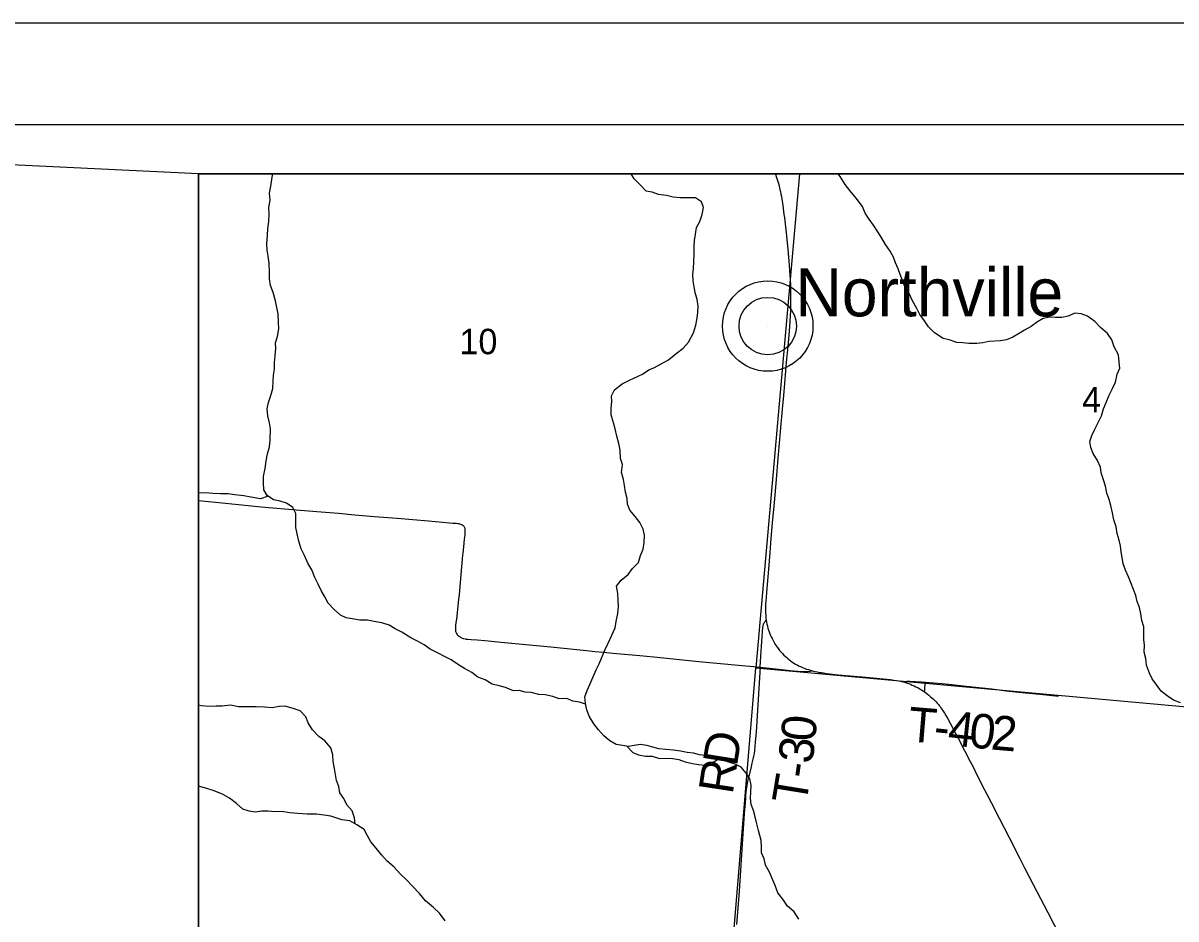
# Model space of a CAD drawing. Extents: x 0 to 1067, y 0 to 440.
# Drawn here: x 113.7 to 227.4, y 351.6 to 440 of the extents above; entities that cross this region are included whole.
import ezdxf

# ---------------------------------------------------------------- set-up
doc = ezdxf.new("R2010")
doc.units = 0
for name, color, linetype in [('GM_X_Minor_River', 7, 'Continuous'), ('GM_X_Section', 7, 'Continuous'), ('GM_X_Section_Text', 7, 'Continuous'), ('GM_X_State_Route', 7, 'Continuous'), ('GM_X_Township_Road', 7, 'Continuous'), ('GM_X_Township_Road_Text', 7, 'Continuous'), ('GM_X_Unincorporated', 7, 'Continuous'), ('GM_X_Unincorporated_Location', 7, 'Continuous'), ('GM_X_Unincorporated_Text', 7, 'Continuous'), ('GM_X_US_Shield', 7, 'Continuous'), ('SC_Scratch1', 7, 'Continuous'), ('SH_Border', 7, 'Continuous'), ('SH_Cut_Line', 7, 'Continuous'), ('SH_Text', 7, 'Continuous')]:
    doc.layers.add(name, color=color, linetype=linetype)

msp = doc.modelspace()

# ---------------------------------------------------------------- linework, layer by layer
at = {"layer": 'GM_X_Minor_River'}
for points in [[(138.15, 423.91), (138.27, 424.79), (138.34, 425.11)], [(173.11, 393.74), (173.02, 394.38), (172.92, 394.98), (172.72, 395.67), (172.83, 396.46), (172.62, 397.06), (172.6, 397.88), (172.46, 398.54), (172.28, 399.25), (172.09, 399.98), (171.93, 400.56), (171.7, 401.34), (171.7, 402.02), (171.76, 402.65), (171.73, 403.22), (172.05, 403.81), (172.79, 404.42), (173.51, 404.78), (174.8, 405.38), (175.41, 405.8), (175.98, 406.03), (176.63, 406.4), (177.35, 406.78), (178.12, 407.4), (178.82, 407.94), (179.34, 408.52), (179.84, 409.44), (180.05, 410.2), (180.2, 410.88), (180.24, 411.45), (180.28, 412.08), (180.19, 412.72), (180, 413.41), (179.88, 413.98), (179.79, 414.58), (179.76, 415.21), (179.82, 415.8), (179.87, 416.46), (179.89, 417.23), (179.89, 417.98), (179.93, 418.55), (180.04, 419.16), (180.13, 419.82), (180.46, 420.44), (180.69, 421.12), (180.82, 421.8), (180.63, 422.37), (180.01, 422.77), (179.39, 422.77), (178.51, 422.77), (177.82, 422.84), (177.15, 423), (176.37, 423.09), (175.74, 423.31), (175.16, 423.42), (174.58, 424.03), (173.96, 424.64), (173.68, 425.11)], [(203.61, 409.43), (203.01, 410.04), (202.6, 410.62), (202.16, 411.25), (201.84, 411.85), (201.43, 412.59), (201.11, 413.31), (200.72, 413.93), (200.48, 414.53), (200.21, 415.2), (200.02, 415.77), (199.76, 416.35), (199.55, 416.92), (199.23, 417.5), (198.75, 418.15), (198.4, 418.77), (198.01, 419.4), (197.57, 420.05), (197.14, 420.67), (196.77, 421.25), (196.49, 421.9), (195.88, 422.71), (195.26, 423.48), (194.78, 424.09), (194.28, 424.87), (194.11, 425.11)], [(169.19, 372.8), (168.59, 373.01), (167.93, 373.1), (167.32, 373.37), (166.59, 373.34), (165.96, 373.57), (165.21, 373.73), (164.58, 373.77), (163.81, 373.95), (163.22, 373.99), (162.63, 374.17), (162.06, 374.14), (161.3, 374.44), (160.66, 374.62), (159.98, 374.77), (159.27, 375.21), (158.57, 375.46), (157.97, 375.95), (157.25, 376.34), (156.56, 376.77), (155.93, 377.17), (155.35, 377.47), (154.57, 377.88), (153.87, 378.24), (153.25, 378.67), (152.53, 379.05), (151.95, 379.35), (151.05, 379.9), (150.4, 380.23), (149.82, 380.59), (149.1, 380.82), (148.51, 380.95), (147.69, 381.09), (146.92, 381.11), (146.17, 381.23), (145.58, 381.34), (145, 381.58), (144.4, 382.15), (143.8, 382.76), (143.46, 383.41), (143.09, 384.03), (142.81, 384.65), (142.47, 385.32), (142.17, 386.06), (141.78, 386.73), (141.46, 387.47), (141.14, 388.14), (140.89, 388.9), (140.75, 389.63), (140.61, 390.23), (140.61, 390.91), (140.6, 391.61), (140.3, 392.21), (139.68, 392.64), (139.07, 392.84), (138.41, 392.98), (137.79, 393.38), (137.46, 393.96), (137.42, 394.64), (137.43, 395.28), (137.59, 396.07), (137.68, 396.8), (137.82, 397.52), (138, 398.2), (138.09, 398.88), (138.1, 399.97), (138.02, 400.58), (137.86, 401.25), (137.79, 401.95), (137.92, 402.56), (138.15, 403.26), (138.33, 403.96), (138.37, 404.66), (138.39, 405.28), (138.5, 405.86), (138.52, 406.5), (138.58, 407.18), (138.65, 407.9), (138.6, 408.47), (138.8, 409.08), (138.94, 409.83), (138.89, 410.49), (138.87, 411.31), (138.75, 411.95), (138.59, 412.61), (138.36, 413.41), (138.11, 414.12), (138.01, 414.78), (138.01, 415.4), (137.97, 416.31), (137.87, 416.99), (137.78, 417.59), (137.75, 418.22), (137.82, 419.06), (137.84, 419.7), (137.95, 420.44), (137.97, 421.15), (137.95, 421.8), (138.08, 422.53), (138.01, 423.23), (138.15, 423.91)], [(227.85, 372.93), (227.17, 373.2), (226.53, 373.65), (225.95, 374.1), (225.51, 374.68), (225.05, 375.31), (224.79, 375.88), (224.52, 376.67), (224.45, 377.31), (224.29, 377.95), (224.31, 378.63), (224.23, 379.2), (224.23, 379.86), (224.25, 380.45), (224.04, 381.05), (223.94, 381.72), (223.8, 382.36), (223.57, 382.93), (223.45, 383.53), (223.22, 384.13), (223.01, 384.73), (222.73, 385.37), (222.43, 386.02), (222.22, 386.64), (222.1, 387.28), (222.01, 387.85), (221.93, 388.42), (221.81, 388.99), (221.6, 389.66), (221.51, 390.3), (221.28, 391.01), (221.14, 391.7), (220.98, 392.41), (220.81, 393), (220.58, 393.63), (220.47, 394.31), (220.26, 394.95), (220.05, 395.62), (219.98, 396.19), (219.68, 396.84), (219.26, 397.55), (219.03, 398.13), (218.93, 398.72), (219.11, 399.33), (219.4, 399.94), (219.72, 400.54), (220.06, 401.26), (220.26, 401.96), (220.53, 402.57), (220.82, 403.29), (221.16, 403.94), (221.45, 404.56), (221.61, 405.38), (221.86, 405.96), (221.81, 406.55), (221.74, 407.28), (221.33, 408.07), (221.08, 408.74), (220.66, 409.38), (219.97, 409.97), (219.4, 410.56), (218.69, 411.1), (218.06, 411.33), (217.44, 411.37), (216.77, 411.09), (216.16, 410.97), (215.52, 410.97), (214.95, 410.99), (214.33, 410.87), (213.75, 410.52), (213.12, 410.08), (212.48, 409.72), (211.89, 409.33), (211.32, 409.02), (210.69, 408.75), (210.12, 408.65), (208.96, 408.59), (208.36, 408.45), (207.77, 408.38), (206.99, 408.38), (206.38, 408.44), (205.79, 408.48), (205.05, 408.75), (204.46, 408.89), (203.61, 409.43)], [(137.88, 393.32), (137.12, 393.08), (136.17, 393.23), (135.49, 393.36), (134.6, 393.46), (133.95, 393.57), (133.17, 393.55), (132.42, 393.59), (131.69, 393.66), (131.01, 393.61), (131, 393.61)], [(190.22, 351.6), (189.77, 352.32), (189.1, 352.89), (188.64, 353.56), (188.16, 354.19), (187.88, 354.91), (187.59, 355.62), (187.33, 356.25), (186.94, 356.94), (186.8, 357.54), (186.54, 358.16), (186.54, 358.73), (186.49, 359.37), (186.25, 360.36), (186.06, 361), (185.92, 361.69), (185.73, 362.31), (185.52, 362.91), (185.45, 363.53), (185.47, 364.14), (185.53, 364.82), (185.37, 365.44), (185.02, 366.02), (184.54, 366.61), (183.93, 366.9), (183.32, 367.08), (182.47, 367.35), (181.83, 367.42), (181.18, 367.71), (180.41, 367.82), (179.82, 367.98), (179.19, 368.04), (178.55, 368.18), (177.87, 368.29), (177.1, 368.33), (176.42, 368.4), (175.83, 368.58), (175.22, 368.73), (174.59, 368.82), (173.99, 368.75), (173.42, 368.65), (172.83, 368.74), (172.2, 368.82), (171.57, 369.18), (170.99, 369.7), (170.46, 370.29), (170, 370.87), (169.55, 371.64), (169.31, 372.24), (169.17, 372.88), (169.1, 373.52), (169.35, 374.17), (169.59, 374.76), (169.91, 375.45), (170.23, 376.19), (170.52, 376.78), (170.74, 377.36), (171.08, 378.15), (171.4, 378.82), (171.76, 379.63), (172.1, 380.33), (172.19, 380.98), (172.37, 381.75), (172.42, 382.46), (172.41, 383.07), (172.36, 383.73), (172.25, 384.44), (172.7, 385.06), (173.37, 385.59), (173.8, 386.19), (174.39, 386.79), (174.61, 387.49), (174.88, 388.09), (174.95, 388.77), (174.99, 389.48), (174.87, 390.07), (174.53, 390.72), (174.09, 391.33), (173.56, 391.96), (173.31, 392.53), (173.28, 393.1), (173.11, 393.74)], [(146.47, 361), (146.41, 361.59), (146.16, 362.28), (145.65, 362.89), (145.35, 363.49), (144.96, 364.08), (144.86, 364.69), (144.63, 365.29), (144.53, 365.87), (144.42, 366.48), (144.3, 367.17), (144.25, 367.81), (144.07, 368.5), (143.47, 369.2), (142.89, 369.63), (142.25, 370.29), (141.84, 370.98), (141.58, 371.56), (141.05, 372.17), (140.33, 372.39), (139.56, 372.62), (138.95, 372.57), (138.28, 372.46), (137.51, 372.5), (136.69, 372.55), (135.85, 372.55), (134.94, 372.54), (134.15, 372.7), (133.35, 372.63), (132.76, 372.63), (132.07, 372.58), (131.32, 372.65), (131, 372.71)], [(173.24, 368.69), (173.26, 368.66), (173.83, 368.05), (174.42, 367.82), (175.08, 367.69), (175.74, 367.67), (176.46, 367.46), (177.17, 367.49), (177.8, 367.45), (178.39, 367.36), (179, 367.11), (179.72, 366.96), (180.34, 366.87), (180.92, 366.78), (181.5, 366.93), (182.19, 367.36), (182.21, 367.38)], [(155.34, 351.45), (154.77, 352.2), (154.19, 352.76), (153.41, 353.4), (152.82, 354.13), (152.09, 354.88), (151.52, 355.47), (150.92, 356.03), (150.26, 356.78), (149.63, 357.32), (149.06, 357.96), (148.53, 358.61), (148.01, 359.22), (147.66, 359.82), (147.34, 360.45), (146.64, 360.9), (145.93, 361.31), (145.15, 361.4), (144.05, 361.76), (143.39, 361.87), (142.64, 361.96), (141.73, 361.96), (140.8, 362.02), (140.03, 362.09), (139.21, 362.22), (138.55, 362.18), (137.87, 362.27), (137.21, 362.26), (136.59, 362.17), (136, 362.25), (135.37, 362.46), (134.77, 363.02), (134.06, 363.54), (133.39, 363.93), (132.44, 364.28), (131.83, 364.48), (131, 364.72)]]:
    msp.add_lwpolyline(points, dxfattribs=at)
at = {"layer": 'GM_X_Section'}
msp.add_lwpolyline([(185.99, 376.41), (246.65, 370.91), (240.78, 310.99), (180.98, 316.33)], close=True, dxfattribs=at)
at = {"layer": 'GM_X_State_Route'}
for points in [[(187.91, 425.11), (187.92, 425.08), (187.99, 424.87), (188.06, 424.67), (188.12, 424.48), (188.17, 424.26), (188.23, 424.07), (188.27, 423.9), (188.31, 423.74), (188.35, 423.56), (188.4, 423.39), (188.45, 423.13), (188.5, 422.89), (188.55, 422.62), (188.61, 422.23), (188.64, 422), (188.75, 421.13), (188.8, 420.82), (188.88, 420.18), (188.96, 419.29), (189.09, 418.03), (189.22, 416.55), (189.29, 415.63), (189.36, 414.66), (189.38, 414.13), (189.4, 413.69), (189.41, 412.63), (189.39, 411.66), (189.37, 411.09), (189.33, 410.59), (189.26, 409.62), (189.13, 408.1), (188.98, 406.5), (188.9, 405.68), (188.8, 404.46), (188.73, 403.65), (188.67, 402.89), (188.61, 402.27), (188.55, 401.53), (188.44, 400.47), (188.38, 399.72), (188.3, 398.92), (188.15, 397.09), (187.97, 394.98), (187.78, 392.69), (187.6, 390.71), (187.47, 389.14), (187.36, 387.77), (187.22, 386.14), (187.02, 383.85), (186.98, 383.32), (186.93, 382.68), (186.92, 382.3), (186.93, 381.89), (186.95, 381.51), (186.97, 381.3), (187, 381.11), (187.03, 380.9), (187.07, 380.7), (187.12, 380.51), (187.17, 380.31), (187.23, 380.12), (187.29, 379.95), (187.37, 379.76), (187.43, 379.6), (187.5, 379.44), (187.58, 379.28), (187.67, 379.09), (187.75, 378.95), (187.86, 378.76), (187.98, 378.58), (188.09, 378.43), (188.2, 378.27), (188.32, 378.11), (188.46, 377.95), (188.61, 377.8), (188.74, 377.66), (188.9, 377.51), (189.02, 377.4), (189.16, 377.27), (189.32, 377.14), (189.43, 377.07), (189.6, 376.96), (189.74, 376.86), (189.89, 376.77), (190.05, 376.68), (190.2, 376.6), (190.37, 376.52), (190.57, 376.43), (190.75, 376.37), (190.98, 376.28), (191.17, 376.22), (191.35, 376.16), (191.57, 376.1), (191.78, 376.05), (192.03, 376), (192.26, 375.95), (192.45, 375.92), (192.66, 375.89), (192.96, 375.85), (193.25, 375.81), (194.1, 375.72), (196.87, 375.47), (198.52, 375.32), (198.92, 375.27), (199.26, 375.23), (199.57, 375.19), (199.86, 375.15), (200.11, 375.1), (200.35, 375.05), (200.55, 375), (200.74, 374.94), (200.91, 374.89), (201.05, 374.84), (201.22, 374.77), (201.41, 374.69), (201.59, 374.61), (201.77, 374.53), (201.94, 374.44), (202.1, 374.35), (202.26, 374.25), (202.5, 374.1), (202.62, 374.01), (202.67, 373.98), (202.87, 373.84), (203.04, 373.7), (203.21, 373.55), (203.35, 373.43), (203.49, 373.3), (203.63, 373.16), (203.75, 373.04), (203.87, 372.91), (203.98, 372.78), (204.05, 372.68), (204.14, 372.57), (204.23, 372.44), (204.31, 372.32), (204.39, 372.21), (204.58, 371.92), (204.71, 371.71), (204.87, 371.43), (205.15, 370.95), (205.97, 369.39), (206.59, 368.16), (207.13, 367.14), (207.37, 366.68)], [(207.37, 366.68), (207.57, 366.26), (208.28, 364.87), (208.75, 363.94), (209.19, 363.1), (209.98, 361.57), (210.96, 359.65), (211.98, 357.66), (212.48, 356.68), (213.33, 355.03), (214.76, 352.26), (216.01, 349.84)]]:
    msp.add_lwpolyline(points, dxfattribs=at)
at = {"layer": 'GM_X_Township_Road'}
for points in [[(252.4, 425.11), (131, 425.11), (131, 200.68)], [(131, 392.89), (133.68, 392.63), (137.18, 392.29), (141.04, 391.96), (143.09, 391.78), (144.82, 391.64), (146.44, 391.5), (148.33, 391.34), (150.6, 391.15), (153.69, 390.89), (155.75, 390.71), (156.1, 390.68), (156.31, 390.67), (156.44, 390.66), (156.58, 390.64), (156.68, 390.62), (156.76, 390.6), (156.84, 390.58), (156.92, 390.55), (156.98, 390.52), (157.05, 390.48), (157.1, 390.44), (157.15, 390.39), (157.18, 390.36), (157.22, 390.31)], [(157.22, 390.31), (157.25, 390.24), (157.27, 390.18), (157.28, 390.13), (157.29, 390.07), (157.29, 389.95), (157.29, 389.87), (157.29, 389.75), (157.28, 389.62), (157.26, 389.49), (157.24, 389.29), (157.22, 389.09), (157.14, 388.34), (157.07, 387.7), (157.06, 387.51), (156.85, 385.21), (156.71, 383.61), (156.66, 383.13), (156.44, 381.21), (156.4, 380.86), (156.36, 380.57), (156.35, 380.43), (156.35, 380.31), (156.34, 380.21), (156.35, 380.11), (156.36, 380.02), (156.38, 379.93), (156.41, 379.85), (156.46, 379.77), (156.51, 379.69), (156.56, 379.62), (156.61, 379.57), (156.67, 379.52), (156.74, 379.48), (156.81, 379.44), (156.88, 379.39), (156.96, 379.35), (157.04, 379.33), (157.1, 379.3), (157.19, 379.28), (157.3, 379.26), (157.42, 379.24), (157.58, 379.23), (157.91, 379.2), (158.49, 379.15), (159.25, 379.08), (160.85, 378.93), (163.3, 378.7), (165.76, 378.46), (169.27, 378.11), (170.11, 378.02), (170.99, 377.93), (171.88, 377.85), (174.55, 377.6), (175.92, 377.47), (180.36, 377.03), (184.26, 376.66), (184.98, 376.59), (185.77, 376.52), (186.4, 376.47)], [(186.4, 376.47), (186.48, 377.55), (186.57, 379), (186.68, 380.44), (186.69, 380.5), (186.7, 380.56), (186.7, 380.62), (186.72, 380.66), (186.74, 380.71), (186.78, 380.8), (186.82, 380.87), (186.87, 380.94), (186.92, 381.01), (187, 381.11)], [(186.4, 376.47), (186.32, 374.91), (186, 370.06), (185.92, 369.1), (185.88, 368.62), (185.84, 368.25), (185.8, 367.96), (185.75, 367.69), (185.68, 367.37), (185.59, 366.99), (185.52, 366.67), (185.44, 366.35), (185.39, 366.1), (185.31, 365.8), (185.23, 365.51), (185.17, 365.23), (185.12, 364.99), (185.09, 364.8), (185.05, 364.58), (185.02, 364.38), (184.99, 364.14), (184.96, 363.84), (184.95, 363.6), (184.91, 363.05), (184.86, 362.41), (184.83, 362), (184.68, 360.03), (184.52, 357.47), (184.44, 355.9), (184.31, 353.9), (184.24, 353.12), (184.08, 351.07)], [(186.4, 376.47), (187.9, 376.3), (189.7, 376.11), (190.56, 376.05), (190.85, 376.04), (191.1, 376.05), (191.31, 376.07), (191.57, 376.1)], [(200.74, 374.94), (200.8, 375.01), (200.84, 375.03), (200.9, 375.07), (200.97, 375.09), (201.02, 375.09), (201.07, 375.09), (201.16, 375.09), (202.27, 375.02), (202.7, 374.98)], [(202.62, 374.01), (202.64, 374.26), (202.69, 374.87), (202.7, 374.98)], [(202.7, 374.98), (204.36, 374.84), (205.01, 374.78), (206.73, 374.6), (209.26, 374.31), (210.68, 374.14), (211.89, 374), (212.93, 373.9), (213.98, 373.81), (215.82, 373.6)]]:
    msp.add_lwpolyline(points, dxfattribs=at)
at = {"layer": 'GM_X_Unincorporated'}
for radius in [4.46, 2.83]:
    msp.add_circle((187.15, 410.11), radius, dxfattribs=at)
at = {"layer": 'GM_X_Unincorporated_Location'}
msp.add_line((187.15, 410.11), (187.15, 410.11), dxfattribs=at)
at = {"layer": 'GM_X_US_Shield'}
msp.add_lwpolyline([(251.95, 425.11), (190.28, 425.11), (185.99, 376.41), (246.65, 370.91)], close=True, dxfattribs=at)
at = {"layer": 'SC_Scratch1'}
msp.add_line((131, 425.11), (30, 430), dxfattribs=at)
at = {"layer": 'SH_Border'}
msp.add_lwpolyline([(30, 430), (670, 430), (670, 10), (30, 10)], close=True, dxfattribs=at)
at = {"layer": 'SH_Cut_Line'}
msp.add_lwpolyline([(0, 0), (680, 0), (680, 440), (0, 440)], close=True, dxfattribs=at)
at = {"layer": 'SH_Text'}
msp.add_lwpolyline([(131, 425.11), (539, 425.11), (539, 17.11), (131, 17.11)], close=True, dxfattribs=at)

# ---------------------------------------------------------------- texts
at = {"layer": 'GM_X_Section_Text'}
for s, height, p in [('10', 2.511, (156.75, 407.33)), ('4', 2.51, (218.15, 401.59))]:
    msp.add_text(s, height=height, rotation=0, dxfattribs=at).set_placement(p)
at = {"layer": 'GM_X_Township_Road_Text'}
for s, rotation, p in [('T', 355.2549, (200.9, 369.16)), ('4', 353.8684, (204.82, 368.8)), ('0', 353.9572, (206.91, 368.58)), ('0', 84.5531, (191.81, 369.04)), ('2', 355.2137, (209.08, 368.35)), ('D', 80.8581, (184.1, 366.6)), ('-', 353.8995, (203.42, 368.95)), ('3', 83.1834, (191.55, 366.86)), ('R', 81.3256, (183.68, 363.84)), ('-', 81.8311, (191.34, 365.39)), ('T', 80.711, (190.92, 362.8))]:
    msp.add_text(s, height=3.41, rotation=rotation, dxfattribs=at).set_placement(p)
at = {"layer": 'GM_X_Unincorporated_Text'}
msp.add_text('Northville', height=4.739, rotation=0, dxfattribs=at).set_placement((189.88, 411.07))

doc.saveas('drawing.dxf')
